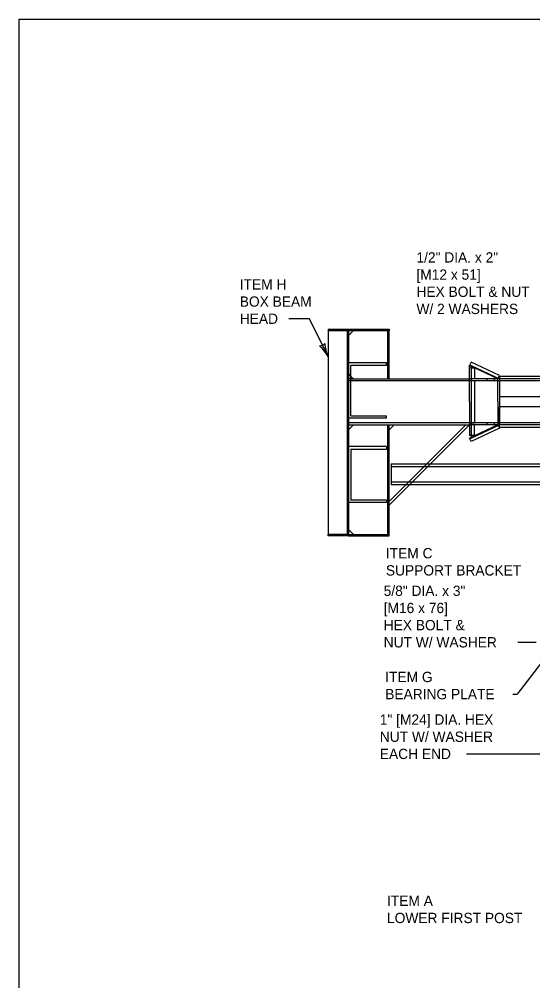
# Model space of a CAD drawing. Extents: x 49991.4 to 50021, y 49987.6 to 50011.4.
# Drawn here: x 49999.38 to 50002.38, y 49993.4 to 49999 of the extents above; entities that cross this region are included whole.
import ezdxf

# ---------------------------------------------------------------- set-up
doc = ezdxf.new("R2010")
doc.units = 0
for name, color, linetype in [('Level 1', 7, 'Continuous'), ('Level 2', 7, 'Continuous'), ('Level 3', 7, 'Continuous'), ('Level 4', 7, 'Continuous')]:
    doc.layers.add(name, color=color, linetype=linetype)

msp = doc.modelspace()

# ---------------------------------------------------------------- linework, layer by layer
at = {"layer": 'Level 1'}
for p, q in [((50001.1835, 49997.1946), (50001.3023, 49997.1946)), ((50001.1835, 49997.1946), (50001.1835, 49997.1866)), ((50001.1835, 49997.1866), (50001.1835, 49995.9985)), ((50001.1835, 49997.1866), (50001.3023, 49997.1866)), ((50001.3023, 49997.1946), (50001.54, 49997.1946)), ((50001.3023, 49997.1866), (50001.3023, 49995.9985)), ((50001.3023, 49997.1866), (50001.54, 49997.1866)), ((50001.3023, 49997.1569), (50001.332, 49997.1866)), ((50001.54, 49997.1946), (50001.54, 49997.1866)), ((50001.54, 49996.9044), (50001.54, 49997.1866)), ((50001.5239, 49996.9978), (50001.3023, 49996.9978)), ((50001.3023, 49996.9941), (50001.3023, 49996.9861)), ((50001.3023, 49996.9933), (50001.3023, 49996.9853)), ((50001.3172, 49996.6896), (50001.3172, 49996.983)), ((50001.5239, 49996.983), (50001.3172, 49996.983)), ((50001.5239, 49996.983), (50001.5239, 49996.9978)), ((50002.0179, 49997.0017), (50002.0085, 49996.9815)), ((50002.0085, 49996.9815), (50002.0179, 49996.9815)), ((50002.0085, 49996.9044), (50002.0085, 49996.9815)), ((50002.1831, 49996.9246), (50002.0179, 49997.0017)), ((50002.0179, 49996.9815), (50002.0179, 49996.5601)), ((50002.0179, 49996.9815), (50002.1831, 49996.9044)), ((50001.3023, 49996.9434), (50001.3023, 49996.9514)), ((50001.3172, 49996.9193), (50001.332, 49996.9044)), ((50002.1754, 49996.908), (50002.1737, 49996.9044)), ((50002.1754, 49996.908), (50002.1831, 49996.9246)), ((50002.6202, 49996.9193), (50002.1831, 49996.9193)), ((50002.1831, 49996.9193), (50002.1831, 49996.8005)), ((50001.3172, 49996.9044), (50001.3023, 49996.9044)), ((50001.3023, 49996.9044), (50001.3023, 49996.6371)), ((50001.3172, 49996.9044), (50001.54, 49996.9044)), ((50001.54, 49996.9044), (50002.0085, 49996.9044)), ((50002.0085, 49996.7708), (50002.0085, 49996.9044)), ((50002.1831, 49996.9044), (50002.1737, 49996.9044)), ((50002.1831, 49996.9044), (50002.1831, 49996.6371)), ((50002.6202, 49996.8005), (50002.1831, 49996.8005)), ((50001.3023, 49996.7296), (50001.3023, 49996.7375)), ((50002.0085, 49996.7708), (50002.0085, 49996.6371)), ((50002.6202, 49996.7411), (50002.1831, 49996.7411)), ((50002.1831, 49996.6222), (50002.1831, 49996.7411)), ((50001.3172, 49996.6896), (50001.5239, 49996.6896)), ((50001.5239, 49996.6748), (50001.5239, 49996.6896)), ((50001.5239, 49996.6748), (50001.3023, 49996.6748)), ((50001.3023, 49996.6074), (50001.332, 49996.6371)), ((50001.3023, 49996.6371), (50001.54, 49996.6371)), ((50001.54, 49996.4231), (50001.54, 49996.6371)), ((50001.54, 49996.6074), (50001.5697, 49996.6371)), ((50001.54, 49996.6371), (50002.0085, 49996.6371)), ((50001.7802, 49996.4088), (50002.0085, 49996.637)), ((50002.0085, 49996.6371), (50002.0085, 49996.5739)), ((50002.0179, 49996.5601), (50002.1831, 49996.6371)), ((50002.1737, 49996.6371), (50002.1831, 49996.6371)), ((50002.1754, 49996.6335), (50002.1737, 49996.6371)), ((50002.1754, 49996.6335), (50002.1831, 49996.6169)), ((50002.0382, 49996.5739), (50002.0085, 49996.5739)), ((50002.1831, 49996.6169), (50002.0179, 49996.5399)), ((50002.6202, 49996.6222), (50002.1831, 49996.6222)), ((50002.0085, 49996.5601), (50002.0179, 49996.5601)), ((50002.0179, 49996.5399), (50002.0085, 49996.5601)), ((50001.5239, 49996.5103), (50001.3023, 49996.5103)), ((50001.3172, 49996.4954), (50001.5239, 49996.4954)), ((50001.3172, 49996.4954), (50001.3172, 49996.1984)), ((50001.5239, 49996.5103), (50001.5239, 49996.4954)), ((50001.54, 49995.9985), (50001.54, 49996.4231)), ((50001.5508, 49996.4088), (50003.6301, 49996.4088)), ((50001.5508, 49996.4088), (50001.5508, 49996.2899)), ((50001.54, 49996.1685), (50001.6614, 49996.2899)), ((50001.5508, 49996.2899), (50003.6301, 49996.2899)), ((50001.5239, 49996.1836), (50001.3023, 49996.1836)), ((50001.5239, 49996.1984), (50001.3172, 49996.1984)), ((50001.5239, 49996.1984), (50001.5239, 49996.1836)), ((50001.3023, 49996.0282), (50001.332, 49995.9985)), ((50001.1835, 49995.9905), (50001.1835, 49995.9985)), ((50001.3023, 49995.9985), (50001.1835, 49995.9985)), ((50001.3023, 49995.9905), (50001.1835, 49995.9905)), ((50001.3023, 49995.9985), (50001.54, 49995.9985)), ((50001.3023, 49995.9905), (50001.54, 49995.9905)), ((50001.54, 49995.9905), (50001.54, 49995.9985))]:
    msp.add_line(p, q, dxfattribs=at)
msp.add_lwpolyline([(49999.3835, 49998.9992), (50016.7501, 49998.9992), (50016.7501, 49987.7988), (49999.3835, 49987.7988)], close=True, dxfattribs=at)
at = {"layer": 'Level 3'}
for p, q in [((50001.0751, 49997.2549), (50000.9551, 49997.2549)), ((50001.1835, 49997.0354), (50001.0751, 49997.2549)), ((50002.7481, 49995.6717), (50002.2871, 49995.0685)), ((50002.2905, 49995.3703), (50002.3974, 49995.3703)), ((50002.26, 49995.0685), (50002.2871, 49995.0685)), ((50001.9905, 49994.7204), (50002.5314, 49994.7204))]:
    msp.add_line(p, q, dxfattribs=at)
for centre, radius, start, end in [((50001.1267, 49997.1504), 0.0548, 278.4314, 314.1537), ((50000.98, 49996.9221), 0.233, 29.1199, 48.3697), ((50001.3867, 49997.1256), 0.2223, 183.7486, 203.9321)]:
    msp.add_arc(centre, radius, start, end, dxfattribs=at)
at = {"layer": 'Level 4'}
for p, q in [((50001.2943, 49997.1866), (50001.2943, 49995.9985)), ((50001.5319, 49996.9044), (50001.5319, 49997.1866)), ((50002.1737, 49996.9044), (50002.0085, 49996.9815)), ((50002.0382, 49996.9676), (50002.0085, 49996.9676)), ((50002.0382, 49996.9676), (50002.0382, 49996.9045)), ((50001.3023, 49996.9341), (50001.3172, 49996.9193)), ((50004.0351, 49996.8933), (50001.3023, 49996.8933)), ((50002.1735, 49996.9045), (50002.0085, 49996.9045)), ((50002.0382, 49996.8933), (50002.0085, 49996.8933)), ((50002.0382, 49996.8933), (50002.0382, 49996.6482)), ((50002.1105, 49996.8933), (50002.1105, 49996.9044)), ((50002.155, 49996.8933), (50002.155, 49996.9044)), ((50002.1737, 49996.7708), (50002.1737, 49996.9044)), ((50002.7178, 49996.9044), (50002.1831, 49996.9044)), ((50001.2943, 49996.8005), (50001.3023, 49996.8005)), ((50001.2943, 49996.7411), (50001.3023, 49996.7411)), ((50002.1737, 49996.7708), (50002.1737, 49996.6371)), ((50003.6301, 49996.6482), (50001.3023, 49996.6482)), ((50001.5319, 49995.9985), (50001.5319, 49996.6371)), ((50001.54, 49996.1895), (50001.9875, 49996.6371)), ((50002.0085, 49996.6482), (50002.0382, 49996.6482)), ((50002.1737, 49996.6371), (50002.0085, 49996.5601)), ((50002.1735, 49996.637), (50002.0085, 49996.637)), ((50002.0382, 49996.5739), (50002.0382, 49996.637)), ((50002.1105, 49996.6371), (50002.1105, 49996.6482)), ((50002.155, 49996.6371), (50002.155, 49996.6482)), ((50002.7178, 49996.6371), (50002.1831, 49996.6371)), ((50001.7802, 49996.4088), (50001.6614, 49996.2899)), ((50001.5508, 49996.3939), (50003.6301, 49996.3939)), ((50001.5508, 49996.3048), (50003.6301, 49996.3048))]:
    msp.add_line(p, q, dxfattribs=at)

# ---------------------------------------------------------------- texts
at = {"layer": 'Level 2'}
for s, p in [('1/2" DIA. x 2" ', (50001.6991, 49997.582)), ('[M12 x 51]', (50001.6991, 49997.482)), ('ITEM H', (50000.6691, 49997.4249)), ('HEX BOLT & NUT', (50001.6991, 49997.382)), ('BOX BEAM', (50000.6691, 49997.3249)), ('W/ 2 WASHERS', (50001.6991, 49997.282)), ('HEAD', (50000.6691, 49997.2249)), ('ITEM C', (50001.5209, 49995.8592)), ('SUPPORT BRACKET', (50001.5209, 49995.7592)), ('5/8" DIA. x 3"', (50001.5081, 49995.6403)), ('[M16 x 76]', (50001.5081, 49995.5403)), ('HEX BOLT &', (50001.5081, 49995.4403)), ('NUT W/ WASHER', (50001.5081, 49995.3403)), ('ITEM G', (50001.517, 49995.1385)), ('BEARING PLATE', (50001.517, 49995.0385)), ('1" [M24] DIA. HEX', (50001.4855, 49994.8904)), ('NUT W/ WASHER', (50001.4855, 49994.7904)), ('EACH END', (50001.4855, 49994.6904)), ('ITEM A', (50001.5275, 49993.8348)), ('LOWER FIRST POST', (50001.5275, 49993.7348))]:
    msp.add_text(s, height=0.06, dxfattribs=at).set_placement(p)

doc.saveas('drawing.dxf')
